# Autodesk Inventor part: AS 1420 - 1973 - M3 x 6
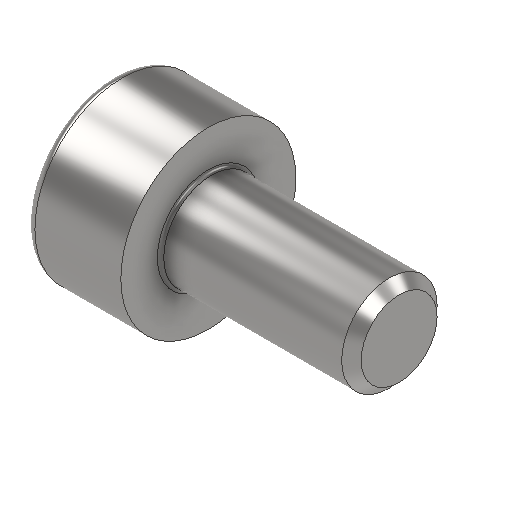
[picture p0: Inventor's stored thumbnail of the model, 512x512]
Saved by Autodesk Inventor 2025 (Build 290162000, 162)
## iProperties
Created: 2021-02
Part Number: AS 1420 - 1973 - M3 x 6
Material: Acciaio, Dolce
Description: Viti con esagono incassato metriche ISO
Document SubType Name: Modeling
Designer: Ryzen5700u
Density: 7.85 g/cm^3
Appearance: Default
Author: Ryzen5700u
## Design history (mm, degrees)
feature "Solid1"
node "Solido1"
